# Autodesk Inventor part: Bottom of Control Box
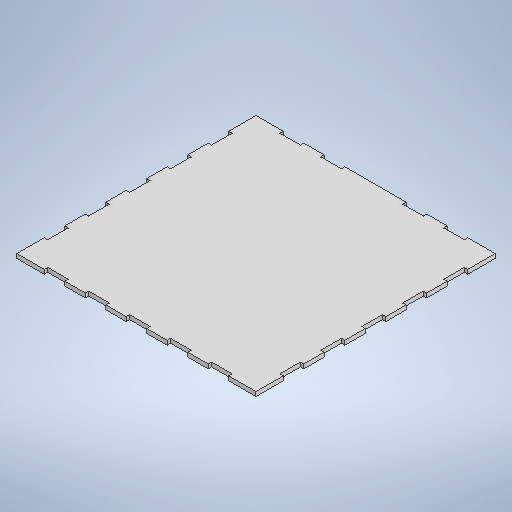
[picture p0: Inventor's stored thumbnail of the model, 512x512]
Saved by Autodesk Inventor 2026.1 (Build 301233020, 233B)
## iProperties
Created: 2026-11
Part Number: Bottom of Control Box
Material: Generic
Document SubType Name: Modeling
Designer: hp
Density: 1 g/cm^3
Appearance: Default
Author: hp
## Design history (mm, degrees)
sketch "Sketch1"
  geometry: L1 (0, 0)-(280, 0); L2 (280, 0)-(280, -280); L3 (280, -280)-(0, -280); L4 (0, -280)-(0, 0); L5 (152, -280)-(128, -280); L6 (128, -280)-(128, -276); L7 (128, -276)-(152, -276); L8 (152, -276)-(152, -280); L9 (104, -280)-(80, -280); L10 (80, -280)-(80, -276); L11 (80, -276)-(104, -276); L12 (104, -276)-(104, -280); L13 (56, -280)-(32, -280); L14 (32, -280)-(32, -276); L15 (32, -276)-(56, -276); L16 (56, -276)-(56, -280); L17 (200, -280)-(176, -280); L18 (176, -280)-(176, -276); L19 (176, -276)-(200, -276); L20 (200, -276)-(200, -280); L21 (152, -280)-(128, -280); L22 (128, -280)-(128, -276); L23 (128, -276)-(152, -276); L24 (152, -276)-(152, -280); L25 (104, -280)-(80, -280); L26 (80, -280)-(80, -276); L27 (80, -276)-(104, -276); L28 (104, -276)-(104, -280); L29 (248, -280)-(224, -280); L30 (224, -280)-(224, -276); L31 (224, -276)-(248, -276); L32 (248, -276)-(248, -280); L33 (200, -280)-(176, -280); L34 (176, -280)-(176, -276); L35 (176, -276)-(200, -276); L36 (200, -276)-(200, -280); L37 (152, -280)-(128, -280); L38 (128, -280)-(128, -276); L39 (128, -276)-(152, -276); L40 (152, -276)-(152, -280); L41 (280, -140)-(0, -140); L42 (140, 0)-(140, -280); L43 (200, -4)-(200, 0); L44 (200, 0)-(176, 0); L45 (176, 0)-(176, -4); L46 (176, -4)-(200, -4); L47 (152, -4)-(152, 0); L48 (152, 0)-(128, 0); L49 (128, 0)-(128, -4); L50 (128, -4)-(152, -4); L51 (56, -4)-(56, 0); L52 (80, 0)-(80, -4); L53 (80, -4)-(104, -4); L54 (104, 0)-(80, 0); L55 (104, -4)-(104, 0); L56 (56, 0)-(32, 0); L57 (32, 0)-(32, -4); L58 (32, -4)-(56, -4); L59 (224, -4)-(248, -4); L60 (248, -4)-(248, 0); L61 (248, 0)-(224, 0); L62 (224, 0)-(224, -4); L63 (152, -4)-(152, 0); L64 (200, 0)-(176, 0)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; 74 further points
  constraints: 300 end point, 90 symmetric about line, 6 midpoint, 6 parallel, 5 horizontal, 3 perpendicular, 2 vertical, 1 point on line
  dimensions: "d0" = 280 distance of L2.end L3.end; "d1" = 280 distance of L1.end L2.end; "d5" = 24 distance of L6.end L7.end; "d6" = 4 distance of L5.end L6.end; "d10" = 48 distance of L5.start L9.start; "d13" = 48 distance of L5.start L17.start; "d16" = 4 distance of L81.end L80.end; "d17" = 24 distance of L80.end L79.end; "d20" = 48 distance of L79.end L83.end; "d23" = 48 distance of L79.end L91.end
extrude "Extrusion1" new body sketch "Sketch1" distance "d3" = 5; taper "d4" = 0 deg
body "Solid1"
node "Sketch Rectangular Pattern1" dims "d10" = 48, "d13" = 48
node "Sketch Rectangular Pattern2" dims "d20" = 48, "d23" = 48
